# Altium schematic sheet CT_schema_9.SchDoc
size 274 x 160 mm
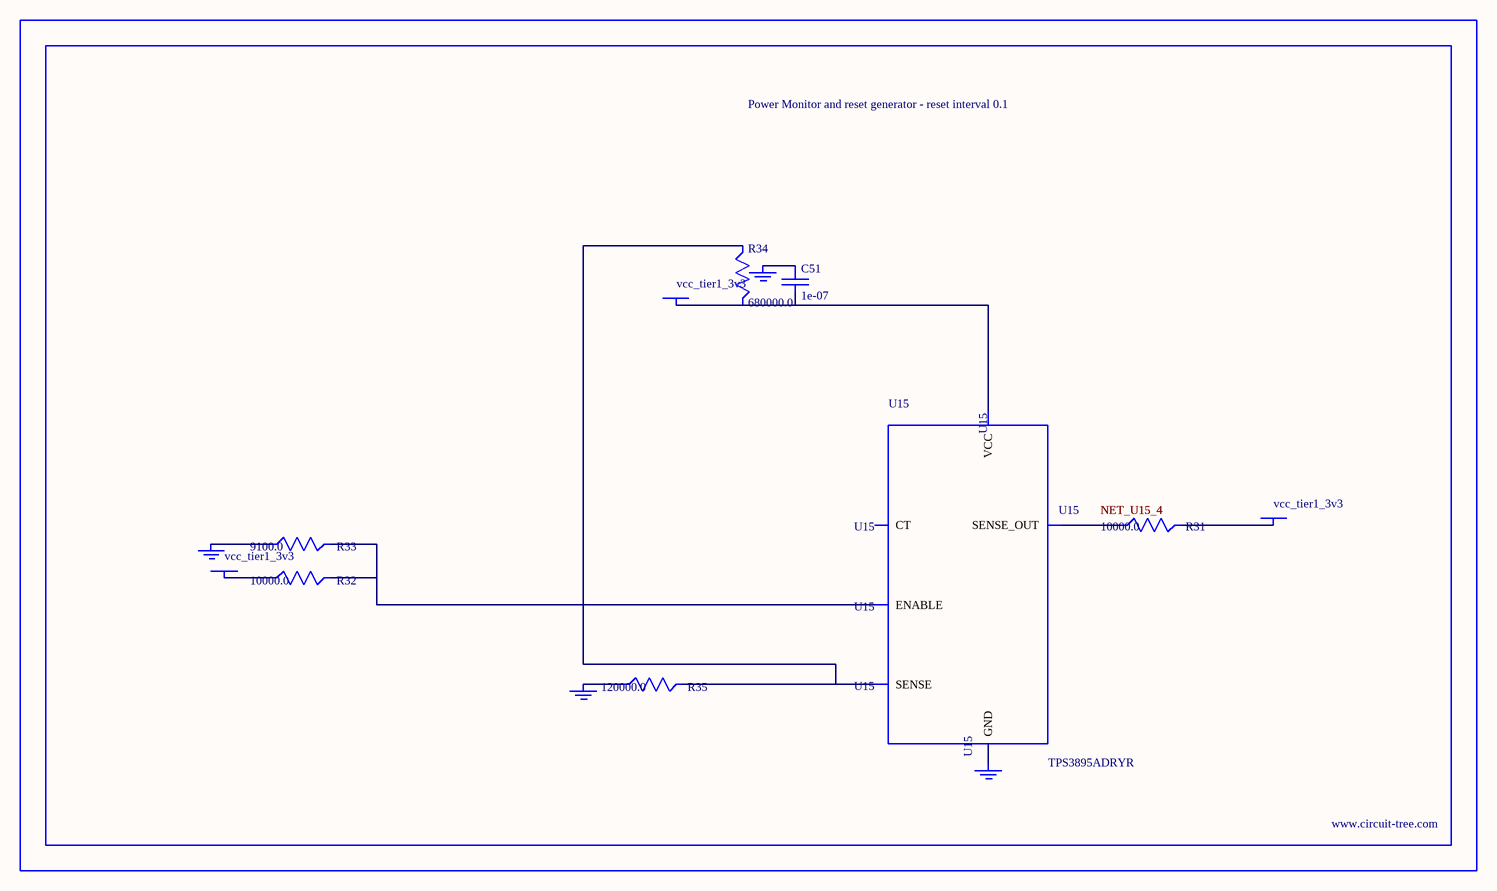
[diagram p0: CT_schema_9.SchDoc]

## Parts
BORDER8  (no value)
C51  1e-07  [C0402]
GND_INSTANCE_8_0  (no value)
GND_INSTANCE_8_1  (no value)
GND_INSTANCE_8_2  (no value)
GND_INSTANCE_8_3  (no value)
POWER_INSTANCE_8_0  vcc_tier1_3v3
POWER_INSTANCE_8_1  vcc_tier1_3v3
POWER_INSTANCE_8_2  vcc_tier1_3v3
R31  10000.0  [R0603]
R32  10000.0  [R0603]
R33  9100.0  [R0603]
R34  680000.0  [R0603]
R35  120000.0  [R0603]
U15  TPS3895ADRYR  [SON-6]

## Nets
NetC51_1: C51.1 GND_INSTANCE_8_2.0(GND)
NetC51_2: C51.2 POWER_INSTANCE_8_2.0(PWR) R34.2 U15.6(VCC)
NetGND_INSTANCE_8_0_0: GND_INSTANCE_8_0.0(GND) R33.1
NetGND_INSTANCE_8_1_0: GND_INSTANCE_8_1.0(GND) R35.1
NetGND_INSTANCE_8_3_0: GND_INSTANCE_8_3.0(GND) U15.2(GND)
NetPOWER_INSTANCE_8_0_0: POWER_INSTANCE_8_0.0(PWR) R32.1
NetPOWER_INSTANCE_8_1_0: POWER_INSTANCE_8_1.0(PWR) R31.2
NetR31_1: R31.1 U15.4(SENSE_OUT)
NetR32_2: R32.2 R33.2 U15.1(ENABLE)
NetR34_1: R34.1 R35.2 U15.3(SENSE)

Not connected (* = marked no-connect by the designer): U15 5(CT)

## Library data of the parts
BORDER8 = BORDER_PAGE8
C51 = C0402C104K3RACTU
GND_INSTANCE_8_0-GND_INSTANCE_8_3 = GND
POWER_INSTANCE_8_0-POWER_INSTANCE_8_2 = PWR
R31 R32 = RC0603JR-0710KL
R33 = RC0603JR-079K1L
R34 = RC0603JR-07680KL
R35 = RC0603JR-07120KL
